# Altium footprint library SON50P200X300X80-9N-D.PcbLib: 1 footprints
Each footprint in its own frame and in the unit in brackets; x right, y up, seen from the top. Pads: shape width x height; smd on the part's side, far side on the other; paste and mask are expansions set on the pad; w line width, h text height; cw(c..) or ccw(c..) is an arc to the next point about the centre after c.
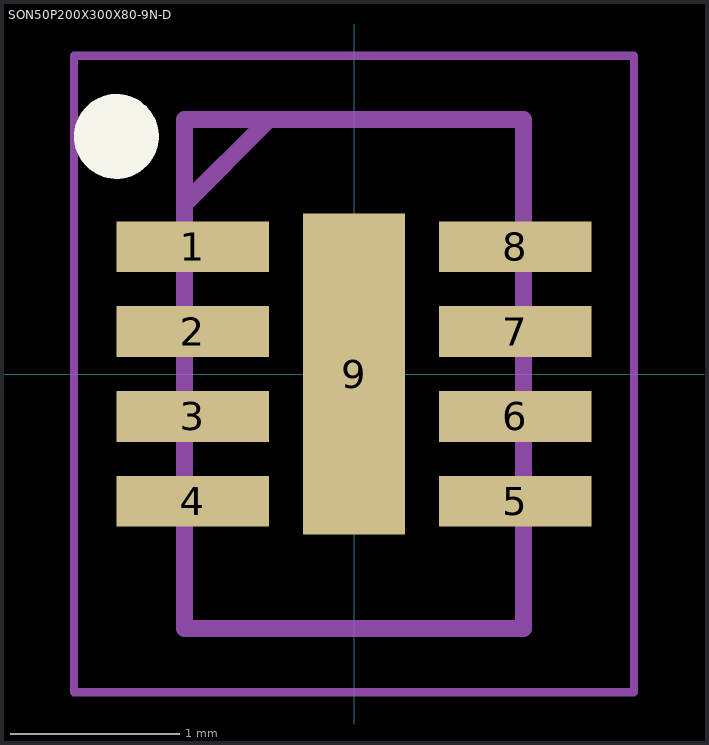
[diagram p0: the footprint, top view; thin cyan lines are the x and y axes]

## SON50P200X300X80-9N-D [mm]
pads (9):
  rect 0.9x0.3 smd: 1(-0.95,0.75) 2(-0.95,0.25) 3(-0.95,-0.25) 4(-0.95,-0.75) 5(0.95,-0.75) 6(0.95,-0.25) 7(0.95,0.25) 8(0.95,0.75)
  rect 0.6x1.89 smd: 9(0,0)
Top Overlay:
  circle w0.25: c-1.4,1.4 r0.125
Mechanical 15:
  lines w0.1: -1,1 -0.5,1.5 ; -1,-1.5 1,-1.5 1,1.5 -1,1.5 -1,-1.5
Mechanical 20:
  lines w0.05: -1.65,-1.875 1.65,-1.875 1.65,1.875 -1.65,1.875 -1.65,-1.875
